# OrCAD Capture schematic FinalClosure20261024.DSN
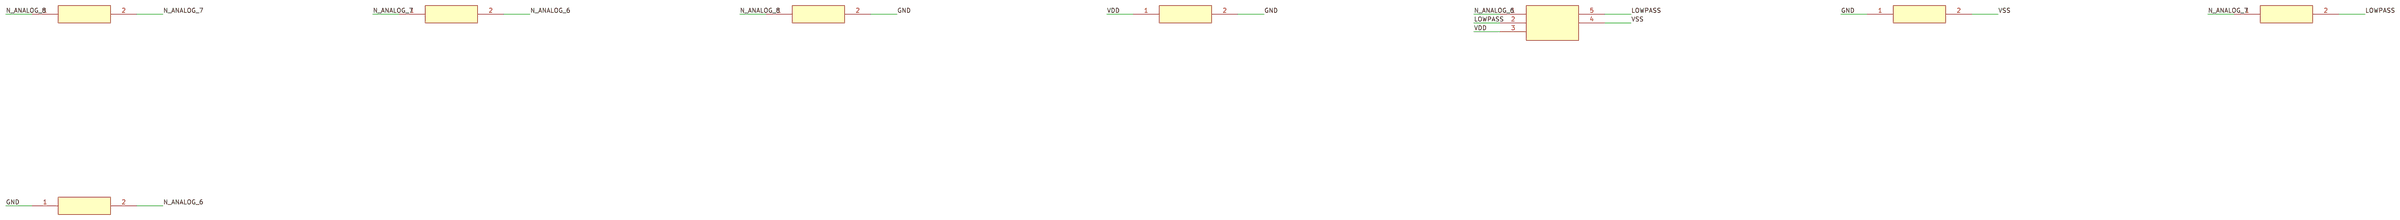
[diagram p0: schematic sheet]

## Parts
C1  100n
C2  100n
R1  1k
R2  1k
U1  AD8051
V1  ac=1
V2  10
V3  10

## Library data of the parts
C1 = OBS_C1
C2 = OBS_C2
R1 = OBS_R1
R2 = OBS_R2
U1 = OBS_U1
V1 = OBS_V1
V2 = OBS_V2
V3 = OBS_V3

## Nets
GND: C2.1 V1.2 V2.2 V3.1
VDD: U1.3 V2.1
VSS: U1.4 V3.2
LOWPASS: C1.2 U1.2 U1.5
N_ANALOG_6: C2.2 R2.2 U1.1
N_ANALOG_7: C1.1 R1.2 R2.1
N_ANALOG_8: R1.1 V1.1
